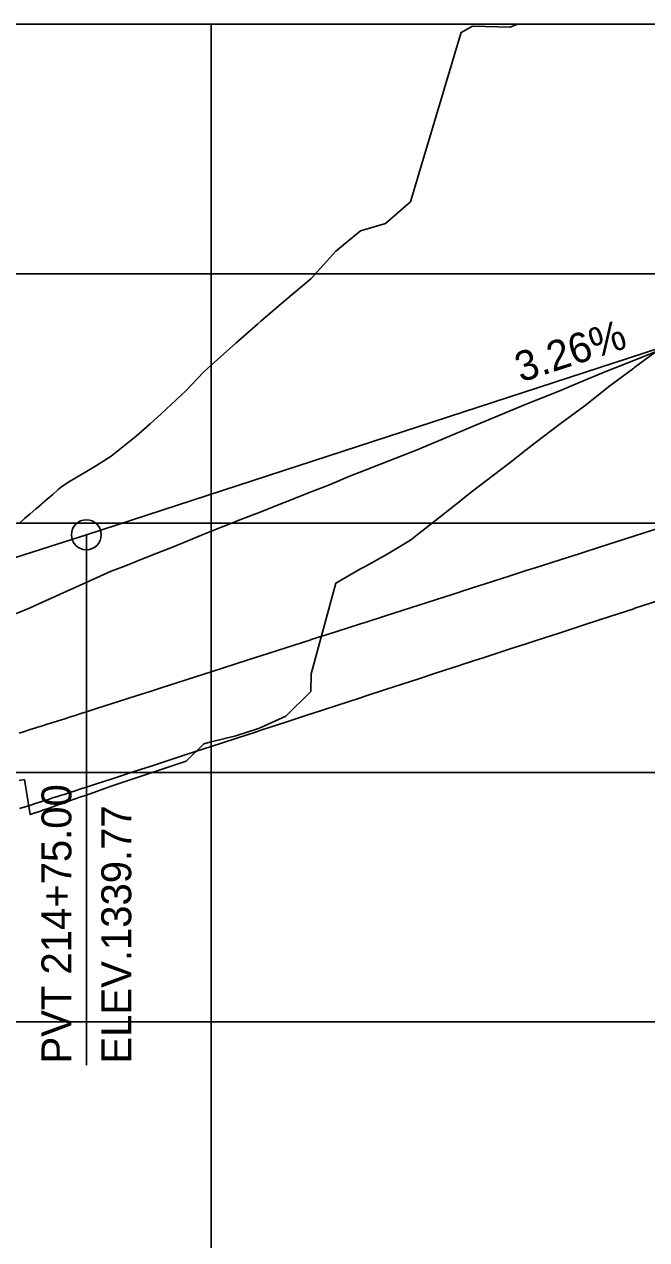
# Model space of a CAD drawing. Extents: x 1371206 to 1374178, y 379328 to 381511.
# Drawn here: x 1372707.2 to 1372832, y 379554.7 to 379798.4 of the extents above; entities that cross this region are included whole.
import ezdxf

# ---------------------------------------------------------------- set-up
doc = ezdxf.new("R2010")
doc.units = 0
for name, color, linetype in [('37', 7, 'Continuous'), ('R_Exist Surface', 7, 'Continuous'), ('R_Profile Work Left', 7, 'Continuous'), ('R_Profile Work Right', 7, 'Continuous'), ('R_Vert Alg', 7, 'Continuous'), ('R_Vert Alg Annot', 7, 'Continuous')]:
    doc.layers.add(name, color=color, linetype=linetype)

msp = doc.modelspace()

# ---------------------------------------------------------------- linework, layer by layer
at = {"layer": '37'}
for p, q in [((1371244.63, 379798.35), (1374144.63, 379798.35)), ((1371244.63, 379798.35), (1374144.63, 379798.35)), ((1372744.63, 379348.35), (1372744.63, 379798.35)), ((1371244.63, 379748.35), (1374144.63, 379748.35)), ((1371244.63, 379698.35), (1374144.63, 379698.35)), ((1371244.63, 379648.35), (1374144.63, 379648.35)), ((1371244.63, 379598.35), (1372944.63, 379598.35)), ((1371244.63, 379598.35), (1374144.63, 379598.35))]:
    msp.add_line(p, q, dxfattribs=at)
at = {"layer": 'R_Exist Surface'}
msp.add_lwpolyline([(1372703.95, 379679.54), (1372708.38, 379681.37), (1372710.86, 379682.49), (1372721.64, 379687.38), (1372724.62, 379688.73), (1372727.17, 379689.68), (1372729.62, 379690.67), (1372732.42, 379691.76), (1372737.26, 379693.63), (1372742.71, 379695.95), (1372743.19, 379696.14), (1372750.96, 379699.18), (1372753.97, 379700.37), (1372764.74, 379704.61), (1372768.36, 379706.03), (1372772.28, 379707.67), (1372775.52, 379708.95), (1372786.29, 379713.2), (1372786.9, 379713.44), (1372793.58, 379716.24), (1372797.07, 379717.7), (1372805.43, 379721.2), (1372807.84, 379722.18), (1372814.24, 379724.76), (1372818.62, 379726.58), (1372823.82, 379728.74), (1372829.39, 379730.98), (1372834.87, 379733.17)], dxfattribs=at)
at = {"layer": 'R_Profile Work Left'}
for points in [[(1372743.19, 379654.11), (1372744.63, 379654.47), (1372749.63, 379655.72), (1372753.97, 379657.09), (1372754.63, 379657.39), (1372759.63, 379659.65), (1372764.63, 379664.56), (1372764.74, 379668.12), (1372769.63, 379686.34), (1372774.63, 379689.16), (1372775.52, 379689.64), (1372779.63, 379691.9), (1372784.63, 379694.95), (1372786.29, 379696.24), (1372789.63, 379698.87), (1372794.63, 379702.82), (1372794.79, 379702.94), (1372797.07, 379704.74), (1372799.63, 379706.69), (1372804.63, 379710.5), (1372807.84, 379713.02), (1372809.63, 379714.43), (1372814.63, 379718.25), (1372818.62, 379721.2), (1372819.63, 379721.96), (1372824.63, 379725.85), (1372829.39, 379729.44), (1372829.63, 379729.61), (1372834.63, 379733.26)], [(1372706.25, 379641.12), (1372707.37, 379641.47), (1372708.48, 379641.82), (1372709.6, 379642.18), (1372709.63, 379642.19), (1372710.71, 379642.53), (1372710.86, 379642.58), (1372711.83, 379642.89), (1372712.94, 379643.25), (1372714.06, 379643.6), (1372714.63, 379643.79), (1372715.17, 379643.96), (1372716.29, 379644.32), (1372717.4, 379644.68), (1372718.52, 379645.04), (1372719.63, 379645.41), (1372721.64, 379646.06), (1372724.63, 379647.04), (1372729.63, 379648.67), (1372732.42, 379649.58), (1372734.63, 379650.3), (1372739.63, 379651.93), (1372743.19, 379653.09), (1372744.63, 379653.56), (1372749.63, 379655.19), (1372753.97, 379656.6), (1372754.63, 379656.82), (1372759.63, 379658.45), (1372764.63, 379660.08), (1372764.74, 379660.12), (1372769.63, 379661.71), (1372774.63, 379663.34), (1372775.52, 379663.63), (1372779.63, 379664.97), (1372784.63, 379666.6), (1372786.29, 379667.14), (1372789.63, 379668.23), (1372794.63, 379669.86), (1372794.79, 379669.91), (1372797.07, 379670.65), (1372799.63, 379671.49), (1372804.63, 379673.12), (1372807.84, 379674.17), (1372809.63, 379674.75), (1372814.63, 379676.38), (1372818.62, 379677.68), (1372819.63, 379678.01), (1372824.63, 379679.64), (1372829.39, 379681.19), (1372829.63, 379681.27), (1372834.63, 379682.9)], [(1372707.25, 379646.95), (1372708.38, 379639.92), (1372709.5, 379640.31), (1372709.63, 379640.35), (1372710.63, 379640.69), (1372710.86, 379640.78), (1372711.75, 379641.08), (1372712.88, 379641.47), (1372714, 379641.86), (1372714.63, 379642.08), (1372715.13, 379642.26), (1372716.25, 379642.65), (1372717.38, 379643.04), (1372718.51, 379643.44), (1372719.63, 379643.83), (1372721.64, 379644.54), (1372724.63, 379645.6), (1372729.63, 379647.31), (1372732.42, 379648.23), (1372734.63, 379648.95), (1372739.63, 379650.6), (1372743.19, 379654.11)], [(1372706.13, 379646.75), (1372707.25, 379646.95)]]:
    msp.add_lwpolyline(points, dxfattribs=at)
at = {"layer": 'R_Profile Work Right'}
for points in [[(1372706.13, 379698.26), (1372707.25, 379699.24), (1372708.38, 379700.21), (1372709.5, 379701.19), (1372709.63, 379701.3), (1372710.63, 379702.16), (1372710.86, 379702.37), (1372711.75, 379703.14), (1372712.88, 379704.11), (1372714, 379705.09), (1372714.63, 379705.63), (1372715.13, 379705.98), (1372716.25, 379706.67), (1372717.38, 379707.35), (1372718.51, 379708.03), (1372719.63, 379708.71), (1372721.64, 379709.93), (1372724.63, 379711.74), (1372729.63, 379715.79), (1372732.42, 379718.27), (1372734.63, 379720.24), (1372739.63, 379724.93), (1372743.19, 379728.68), (1372744.63, 379730.04), (1372749.63, 379734.43), (1372753.97, 379738.22), (1372754.63, 379738.81), (1372759.63, 379743.09), (1372764.63, 379747.3), (1372764.74, 379747.39), (1372769.63, 379752.85), (1372774.63, 379756.97), (1372775.52, 379757.23), (1372779.63, 379758.41), (1372784.63, 379762.78), (1372786.29, 379768.34), (1372789.63, 379779.52), (1372794.63, 379796.3), (1372794.79, 379796.74), (1372797.07, 379797.95), (1372799.63, 379797.89), (1372804.63, 379797.78), (1372806.06, 379798.35)], [(1372706.13, 379656.25), (1372707.25, 379656.6), (1372708.38, 379656.95), (1372709.5, 379657.3), (1372709.63, 379657.34), (1372710.63, 379657.65), (1372710.86, 379657.73), (1372711.75, 379658.01), (1372712.88, 379658.36), (1372714, 379658.72), (1372714.63, 379658.92), (1372715.13, 379659.07), (1372716.25, 379659.43), (1372717.38, 379659.79), (1372718.51, 379660.15), (1372719.63, 379660.51), (1372721.64, 379661.16), (1372724.63, 379662.12), (1372729.63, 379663.72), (1372732.42, 379664.61), (1372734.63, 379665.32), (1372739.63, 379666.93), (1372743.19, 379668.07), (1372744.63, 379668.53), (1372749.63, 379670.14), (1372753.97, 379671.53), (1372754.63, 379671.74), (1372759.63, 379673.35), (1372764.63, 379674.95), (1372764.74, 379674.99), (1372769.63, 379676.56), (1372774.63, 379678.16), (1372775.52, 379678.45), (1372779.63, 379679.77), (1372784.63, 379681.37), (1372786.29, 379681.9), (1372789.63, 379682.97), (1372794.63, 379684.58), (1372794.79, 379684.63), (1372797.07, 379685.36), (1372799.63, 379686.18), (1372804.63, 379687.79), (1372807.84, 379688.82), (1372809.63, 379689.39), (1372814.63, 379691), (1372818.62, 379692.28), (1372819.63, 379692.6), (1372824.63, 379694.21), (1372829.39, 379695.73), (1372829.63, 379695.81), (1372834.63, 379697.42)]]:
    msp.add_lwpolyline(points, dxfattribs=at)
at = {"layer": 'R_Vert Alg'}
msp.add_line((1372719.63, 379696.01), (1372921.37, 379761.78), dxfattribs=at)
msp.add_lwpolyline([(1372566.51, 379655.58), (1372573.8, 379657.08), (1372581.09, 379658.62), (1372588.38, 379660.2), (1372595.67, 379661.82), (1372602.96, 379663.49), (1372610.26, 379665.19), (1372617.55, 379666.95), (1372624.84, 379668.74), (1372632.13, 379670.58), (1372639.42, 379672.46), (1372646.71, 379674.39), (1372654.01, 379676.36), (1372661.3, 379678.37), (1372668.59, 379680.42), (1372675.88, 379682.52), (1372683.17, 379684.66), (1372690.46, 379686.84), (1372697.76, 379689.07), (1372705.05, 379691.34), (1372712.34, 379693.65), (1372719.63, 379696.01)], dxfattribs=at)
msp.add_circle((1372719.63, 379696.01), 3, dxfattribs=at)
at = {"layer": 'R_Vert Alg Annot'}
msp.add_line((1372719.63, 379696.01), (1372719.63, 379589.65), dxfattribs=at)

# ---------------------------------------------------------------- texts
for s, rotation, p in [('3.26%', 18.0578, (1372806.76, 379726.52)), ('PVT 214+75.00', 90, (1372716.63, 379590.01)), ('ELEV.1339.77', 90, (1372728.63, 379590.01))]:
    msp.add_text(s, height=6, rotation=rotation, dxfattribs=at).set_placement(p)

doc.saveas('drawing.dxf')
